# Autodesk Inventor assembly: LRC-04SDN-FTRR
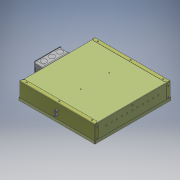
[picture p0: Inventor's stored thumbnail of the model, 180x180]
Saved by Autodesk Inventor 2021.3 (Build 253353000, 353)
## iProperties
description: 0:0:Super Shallow 4" Downlight - COB LED
manufacturer: 0:0:The Kirlin Company
model: 0:0:LRC-04SDN
url: 0:0:
Part Number: LRC-04SDN-FTRR
Document SubType Name: Assembly
Designer: JChurch
load_classification: Lighting
motor: 0 ul
Author: JChurch
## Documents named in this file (5)
- X:\Revit Files\0000-Un-Zipped\COB\LRC-04SDN-FTR\LRC-04SDN-FTRR.iam
- X:\INVENTOR\885\885000-00-00.iam
- X:\INVENTOR\830\830520-00-00.ipt
- X:\INVENTOR\750\750480-FT-XX.iam
- X:\Revit Files\0000-Un-Zipped\COB\LRC-04SDN-FTR\LRC-04SDN-FTRR_Substitute_1.ipt
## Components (4 placed, 4 different names)
1. 885000-00-00:1 [sub-assembly] — Mate:4, Mate:5, Angle:1
2. 830520-00-00:1 — Mate:1, Mate:2, Mate:3, Mate:4, Mate:5, Angle:1, Insert:1
3. 750480-FT-XX:1 [sub-assembly] — Insert:1
4. LRC-04SDN-FTRR_Substitute_1:1
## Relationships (7: Mate 5, Angle 1, Insert 1)
- Mate:1: 830520-00-00:1
- Mate:2: 830520-00-00:1
- Mate:3: 830520-00-00:1
- Mate:4: 885000-00-00:1 ↔ 830520-00-00:1
- Mate:5: 885000-00-00:1 ↔ 830520-00-00:1
- Angle:1: 885000-00-00:1 ↔ 830520-00-00:1
- Insert:1: 830520-00-00:1 ↔ 750480-FT-XX:1
